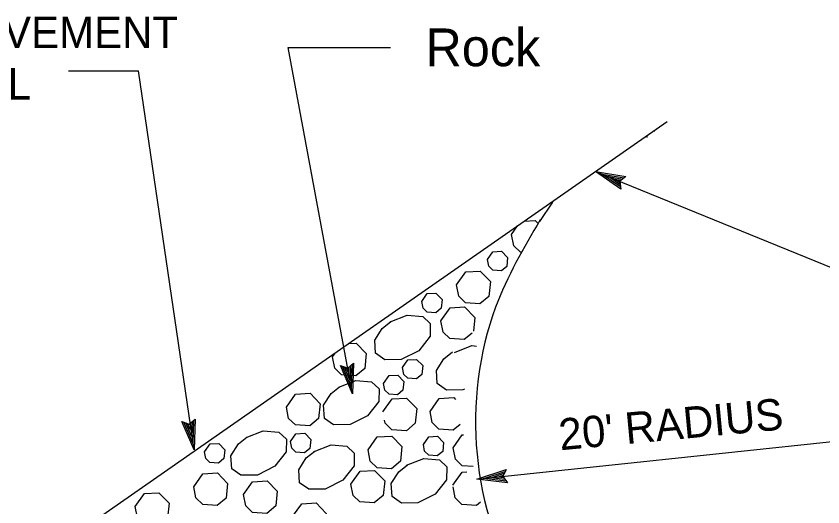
# Model space of a CAD drawing. Extents: x 6709491 to 6710959, y 1869789 to 1870763.
# Drawn here: x 6710597.8 to 6710751.9, y 1870434.5 to 1870528.2 of the extents above; entities that cross this region are included whole.
import ezdxf

# ---------------------------------------------------------------- set-up
doc = ezdxf.new("R2010")
doc.units = 0
for name, color, linetype in [('56 Stg 3 Anno', 7, 'Continuous'), ('57 Undefined', 7, 'Continuous'), ('60 Nongeo Data', 7, 'Continuous')]:
    doc.layers.add(name, color=color, linetype=linetype)

msp = doc.modelspace()

# ---------------------------------------------------------------- linework, layer by layer
at = {"layer": '56 Stg 3 Anno'}
for p, q in [((6710662.04, 1870456.06), (6710649.77, 1870522.23)), ((6710649.77, 1870522.23), (6710669.31, 1870522.23)), ((6710607.82, 1870517.73), (6710621.17, 1870517.73)), ((6710631.77, 1870445.38), (6710621.17, 1870517.73)), ((6710708.46, 1870498.55), (6710951.94, 1870399.33)), ((6710713.31, 1870495.18), (6710708.46, 1870498.55)), ((6710708.46, 1870498.55), (6710708.46, 1870498.55)), ((6710708.46, 1870498.55), (6710714.27, 1870497.56)), ((6710713.24, 1870495.58), (6710709.68, 1870498.05)), ((6710709.7, 1870498.05), (6710713.94, 1870497.32)), ((6710713.17, 1870495.98), (6710710.91, 1870497.55)), ((6710710.91, 1870497.55), (6710713.65, 1870497.08)), ((6710713.13, 1870496.36), (6710712.14, 1870497.05)), ((6710712.14, 1870497.05), (6710713.31, 1870496.85)), ((6710714.27, 1870497.56), (6710713.08, 1870496.67)), ((6710714.27, 1870497.56), (6710714.27, 1870497.56)), ((6710713.08, 1870496.67), (6710713.31, 1870495.18)), ((6710713.31, 1870495.18), (6710713.31, 1870495.18)), ((6710662.04, 1870456.06), (6710659.73, 1870461.49)), ((6710659.73, 1870461.49), (6710659.73, 1870461.49)), ((6710659.73, 1870461.49), (6710661.13, 1870460.96)), ((6710661.13, 1870460.96), (6710662.25, 1870461.95)), ((6710661.66, 1870461.4), (6710661.56, 1870458.66)), ((6710661.95, 1870461.69), (6710661.8, 1870457.36)), ((6710662.25, 1870461.95), (6710662.04, 1870456.06)), ((6710662.25, 1870461.95), (6710662.25, 1870461.95)), ((6710661.79, 1870457.37), (6710660.11, 1870461.33)), ((6710661.56, 1870458.66), (6710660.47, 1870461.22)), ((6710661.32, 1870459.97), (6710660.85, 1870461.06)), ((6710661.36, 1870461.18), (6710661.32, 1870459.97)), ((6710662.04, 1870456.06), (6710662.04, 1870456.06)), ((6710631.77, 1870445.38), (6710629.46, 1870450.81)), ((6710629.46, 1870450.81), (6710629.46, 1870450.81)), ((6710629.46, 1870450.81), (6710630.86, 1870450.29)), ((6710631.52, 1870446.69), (6710629.84, 1870450.65)), ((6710631.29, 1870447.99), (6710630.2, 1870450.54)), ((6710630.86, 1870450.29), (6710631.98, 1870451.28)), ((6710631.39, 1870450.73), (6710631.29, 1870447.99)), ((6710631.68, 1870451.01), (6710631.53, 1870446.68)), ((6710631.98, 1870451.28), (6710631.77, 1870445.38)), ((6710631.98, 1870451.28), (6710631.98, 1870451.28)), ((6710631.05, 1870449.29), (6710630.58, 1870450.38)), ((6710631.09, 1870450.5), (6710631.05, 1870449.29)), ((6710685.79, 1870439.79), (6710776.98, 1870449.42)), ((6710631.77, 1870445.38), (6710631.77, 1870445.38)), ((6710685.79, 1870439.79), (6710691.39, 1870441.66)), ((6710685.79, 1870439.79), (6710691.39, 1870441.66)), ((6710691.39, 1870441.66), (6710690.76, 1870440.31)), ((6710691.39, 1870441.66), (6710690.76, 1870440.31)), ((6710691.39, 1870441.66), (6710691.39, 1870441.66)), ((6710691.39, 1870441.66), (6710691.39, 1870441.66)), ((6710691.66, 1870439.11), (6710685.79, 1870439.79)), ((6710685.79, 1870439.79), (6710685.79, 1870439.79)), ((6710691.66, 1870439.11), (6710685.79, 1870439.79)), ((6710685.79, 1870439.79), (6710685.79, 1870439.79)), ((6710691.41, 1870439.43), (6710687.11, 1870439.92)), ((6710691.41, 1870439.43), (6710687.11, 1870439.92)), ((6710687.12, 1870439.93), (6710691.2, 1870441.29)), ((6710687.12, 1870439.93), (6710691.2, 1870441.29)), ((6710688.43, 1870440.06), (6710691.06, 1870440.95)), ((6710688.43, 1870440.06), (6710691.06, 1870440.95)), ((6710691.15, 1870439.75), (6710688.43, 1870440.06)), ((6710691.15, 1870439.75), (6710688.43, 1870440.06)), ((6710689.75, 1870440.2), (6710690.88, 1870440.58)), ((6710689.75, 1870440.2), (6710690.88, 1870440.58)), ((6710690.95, 1870440.06), (6710689.75, 1870440.2)), ((6710690.95, 1870440.06), (6710689.75, 1870440.2)), ((6710690.76, 1870440.31), (6710691.66, 1870439.11)), ((6710690.76, 1870440.31), (6710691.66, 1870439.11)), ((6710691.66, 1870439.11), (6710691.66, 1870439.11)), ((6710691.66, 1870439.11), (6710691.66, 1870439.11))]:
    msp.add_line(p, q, dxfattribs=at)
at = {"layer": '60 Nongeo Data'}
for p, q in [((6710451.72, 1870319.56), (6710722.11, 1870508.07)), ((6710697.84, 1870488.99), (6710700.28, 1870492.69))]:
    msp.add_line(p, q, dxfattribs=at)
for points in [[(6710719.71, 1870506.18), (6710719.58, 1870506.31)], [(6710718.27, 1870505.39), (6710718.26, 1870505.05)], [(6710694.81, 1870489.03), (6710696.93, 1870489.15), (6710697.55, 1870488.51)], [(6710692.41, 1870486.52), (6710693.57, 1870488.17)], [(6710694.26, 1870483.11), (6710694.12, 1870483.12), (6710692.83, 1870484.37), (6710692.41, 1870486.52)], [(6710687.8, 1870481.72), (6710688.85, 1870483.21), (6710690.51, 1870483.3), (6710691.67, 1870482.1), (6710691.5, 1870480.42), (6710690.47, 1870479.56), (6710688.83, 1870479.68), (6710688.05, 1870480.43), (6710687.8, 1870481.72)], [(6710681.92, 1870476.88), (6710683.66, 1870479.35), (6710686.44, 1870479.51), (6710688.37, 1870477.51), (6710688.09, 1870474.7), (6710686.37, 1870473.28), (6710683.63, 1870473.47), (6710682.34, 1870474.73), (6710681.92, 1870476.88)], [(6710675.27, 1870473.74), (6710676.31, 1870475.23), (6710677.98, 1870475.32), (6710679.14, 1870474.12), (6710678.97, 1870472.44), (6710677.94, 1870471.58), (6710676.29, 1870471.7), (6710675.52, 1870472.45), (6710675.27, 1870473.74)], [(6710678.93, 1870470.04), (6710680.67, 1870472.51), (6710683.45, 1870472.67), (6710685.38, 1870470.67), (6710685.12, 1870468.07)], [(6710669.23, 1870469.81), (6710672.48, 1870471.1), (6710675.47, 1870470.84), (6710676.89, 1870469.49), (6710676.85, 1870467.07), (6710674.69, 1870464.31), (6710671.36, 1870462.65), (6710668.22, 1870462.59), (6710666.45, 1870463.85), (6710666.28, 1870466.35), (6710667.72, 1870468.59), (6710669.36, 1870469.9)], [(6710684.89, 1870467.69), (6710683.38, 1870466.44), (6710680.64, 1870466.64), (6710679.35, 1870467.89), (6710678.93, 1870470.04)], [(6710661.31, 1870465.68), (6710662.74, 1870465.76), (6710664.67, 1870463.76), (6710664.39, 1870460.95), (6710662.67, 1870459.52), (6710659.93, 1870459.72), (6710658.64, 1870460.97), (6710658.22, 1870463.12)], [(6710681.55, 1870464), (6710684.8, 1870465.29), (6710685.74, 1870465.21)], [(6710658.22, 1870463.12), (6710658.78, 1870463.91)], [(6710683.45, 1870457), (6710683.12, 1870456.83), (6710679.98, 1870456.78), (6710678.21, 1870458.03), (6710678.05, 1870460.54), (6710679.48, 1870462.77), (6710681.12, 1870464.08)], [(6710671.57, 1870461.1), (6710672.61, 1870462.58), (6710674.28, 1870462.67), (6710675.44, 1870461.47), (6710675.27, 1870459.79), (6710674.24, 1870458.93), (6710672.6, 1870459.05), (6710671.82, 1870459.8), (6710671.57, 1870461.1)], [(6710659.44, 1870457.37), (6710662.69, 1870458.66), (6710665.68, 1870458.4), (6710667.1, 1870457.05), (6710667.06, 1870454.63), (6710664.9, 1870451.87), (6710661.57, 1870450.21), (6710658.43, 1870450.15), (6710656.66, 1870451.41), (6710656.49, 1870453.91), (6710657.93, 1870456.14), (6710659.57, 1870457.45)], [(6710667.98, 1870458.08), (6710669.03, 1870459.56), (6710670.69, 1870459.66), (6710671.85, 1870458.46), (6710671.68, 1870456.77), (6710670.65, 1870455.92), (6710669.01, 1870456.04), (6710668.23, 1870456.79), (6710667.98, 1870458.08)], [(6710649.41, 1870453.56), (6710651.15, 1870456.03), (6710653.92, 1870456.19), (6710655.85, 1870454.19), (6710655.57, 1870451.38), (6710653.86, 1870449.96), (6710651.12, 1870450.16), (6710649.83, 1870451.41), (6710649.41, 1870453.56)], [(6710667.86, 1870452.64), (6710669.6, 1870455.11), (6710672.38, 1870455.27), (6710674.31, 1870453.27), (6710674.03, 1870450.47), (6710672.32, 1870449.04), (6710669.58, 1870449.24), (6710668.28, 1870450.49), (6710668.17, 1870451.06)], [(6710676.84, 1870452.74), (6710678.58, 1870455.22), (6710681.36, 1870455.37), (6710681.69, 1870455.03)], [(6710682.61, 1870450.24), (6710681.29, 1870449.14), (6710678.55, 1870449.34), (6710677.26, 1870450.59), (6710676.84, 1870452.74)], [(6710641.74, 1870447.75), (6710645, 1870449.04), (6710647.99, 1870448.78), (6710649.41, 1870447.43), (6710649.36, 1870445.01), (6710647.21, 1870442.25), (6710643.87, 1870440.58), (6710640.73, 1870440.53), (6710638.97, 1870441.78), (6710638.8, 1870444.28), (6710640.23, 1870446.52), (6710641.88, 1870447.83)], [(6710650.2, 1870446.98), (6710651.24, 1870448.47), (6710652.91, 1870448.56), (6710654.07, 1870447.36), (6710653.9, 1870445.68), (6710652.87, 1870444.82), (6710651.23, 1870444.94), (6710650.45, 1870445.69), (6710650.2, 1870446.98)], [(6710665.01, 1870445.39), (6710666.75, 1870447.87), (6710669.53, 1870448.03), (6710671.46, 1870446.03), (6710671.18, 1870443.22), (6710669.46, 1870441.79), (6710666.72, 1870441.99), (6710665.43, 1870443.24), (6710665.01, 1870445.39)], [(6710675.57, 1870446.41), (6710676.61, 1870447.9), (6710678.28, 1870447.99), (6710679.43, 1870446.79), (6710679.27, 1870445.11), (6710678.24, 1870444.25), (6710676.59, 1870444.37), (6710675.82, 1870445.12), (6710675.57, 1870446.41)], [(6710681.27, 1870445.77), (6710683.01, 1870448.25), (6710683.23, 1870448.26)], [(6710633.78, 1870445.04), (6710634.82, 1870446.53), (6710636.49, 1870446.62), (6710637.64, 1870445.42), (6710637.48, 1870443.74), (6710636.45, 1870442.88), (6710634.8, 1870443), (6710634.03, 1870443.75), (6710633.78, 1870445.04)], [(6710654.71, 1870445.08), (6710657.96, 1870446.37), (6710660.95, 1870446.11), (6710662.37, 1870444.76), (6710662.33, 1870442.33), (6710660.17, 1870439.58), (6710656.84, 1870437.91), (6710653.7, 1870437.86), (6710651.93, 1870439.11), (6710651.76, 1870441.61), (6710653.2, 1870443.85), (6710654.84, 1870445.16)], [(6710685.11, 1870442.21), (6710682.98, 1870442.37), (6710681.69, 1870443.62), (6710681.27, 1870445.77)], [(6710672.38, 1870442.45), (6710675.64, 1870443.74), (6710678.63, 1870443.48), (6710680.05, 1870442.13), (6710680, 1870439.7), (6710677.85, 1870436.95), (6710674.51, 1870435.28), (6710671.37, 1870435.23), (6710669.61, 1870436.48), (6710669.44, 1870438.98), (6710670.87, 1870441.22), (6710672.52, 1870442.53)], [(6710661.74, 1870438.85), (6710663.48, 1870441.32), (6710666.26, 1870441.48), (6710668.19, 1870439.48), (6710667.91, 1870436.68), (6710666.19, 1870435.25), (6710663.45, 1870435.45), (6710662.16, 1870436.7), (6710661.74, 1870438.85)], [(6710631.71, 1870438.36), (6710633.45, 1870440.84), (6710636.23, 1870441), (6710638.16, 1870439), (6710637.88, 1870436.19), (6710636.16, 1870434.76), (6710633.42, 1870434.96), (6710632.13, 1870436.21), (6710631.71, 1870438.36)], [(6710681.23, 1870438.64), (6710682.97, 1870441.12), (6710683.86, 1870441.17)], [(6710641.22, 1870436.85), (6710642.96, 1870439.32), (6710645.73, 1870439.48), (6710647.66, 1870437.48), (6710647.39, 1870434.68), (6710645.67, 1870433.25), (6710642.93, 1870433.45), (6710641.64, 1870434.7), (6710641.22, 1870436.85)], [(6710686.46, 1870435.41), (6710685.69, 1870434.76), (6710682.94, 1870434.96), (6710681.65, 1870436.21), (6710681.24, 1870438.36)], [(6710620.55, 1870434.58), (6710622.29, 1870437.06), (6710625.06, 1870437.22), (6710627, 1870435.21), (6710626.72, 1870432.41), (6710625, 1870430.98), (6710622.26, 1870431.18), (6710620.97, 1870432.43), (6710620.55, 1870434.58)], [(6710650.59, 1870432.64), (6710652.33, 1870435.12), (6710655.1, 1870435.27), (6710657.03, 1870433.27), (6710656.75, 1870430.47), (6710655.04, 1870429.04), (6710652.3, 1870429.24), (6710651.01, 1870430.49), (6710650.59, 1870432.64)]]:
    msp.add_lwpolyline(points, dxfattribs=at)
msp.add_spline([(6710697.88, 1870489.28), (6710689.36, 1870472.63), (6710694.81, 1870418.08), (6710703.29, 1870407.78)], degree=3, dxfattribs=at)

# ---------------------------------------------------------------- texts
at = {"layer": '57 Undefined'}
for s, height, p in [('EXCAVATE TO CONFORM TO PAVEMENT ', 6, (6710469.13, 1870522.1)), ('Rock', 7.2, (6710675.96, 1870518.63)), ('OR CURB, SEE CONFORM DETAIL', 6, (6710469.13, 1870512.26))]:
    msp.add_text(s, height=height, dxfattribs=at).set_placement(p)
msp.add_text("20' RADIUS", height=6, rotation=5.3581, dxfattribs=at).set_placement((6710701.72, 1870445.3))

doc.saveas('drawing.dxf')
